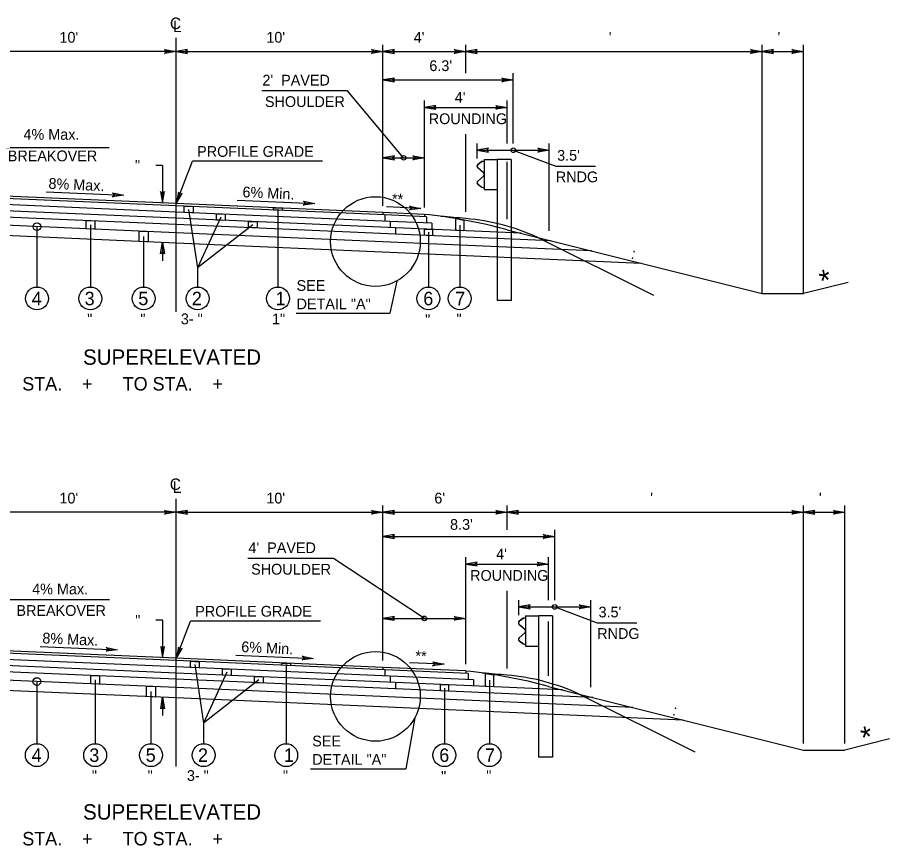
# Model space of a CAD drawing. Extents: x -592 to 1199, y -590 to 416.
# Drawn here: x 524 to 637.5, y -214.2 to -106.3 of the extents above; entities that cross this region are included whole.
import ezdxf

# ---------------------------------------------------------------- set-up
doc = ezdxf.new("R2010")
doc.units = 0
doc.layers.add('1', color=7, linetype='Continuous')
doc.layers.add('Des_ Drain_ Ftrs', color=7, linetype='Continuous')

msp = doc.modelspace()

# ---------------------------------------------------------------- linework, layer by layer
at = {"layer": '1'}
for p, q in [((544.62, -144.63), (544.62, -108.97)), ((571.56, -130.83), (571.56, -109.85)), ((582.34, -113.56), (582.34, -109.85)), ((620.92, -142.25), (620.92, -109.85)), ((626.31, -142.25), (626.31, -109.85)), ((544.62, -110.73), (517.68, -110.73)), ((544.62, -110.73), (571.56, -110.73)), ((571.56, -110.73), (582.34, -110.73)), ((582.34, -110.73), (620.92, -110.73)), ((620.92, -110.73), (626.31, -110.73)), ((588.53, -122.71), (588.53, -113.56)), ((571.56, -114.44), (588.53, -114.44)), ((566.92, -115.86), (555.78, -115.86)), ((574.25, -124.58), (566.92, -115.86)), ((576.95, -131.07), (576.95, -117.13)), ((576.95, -118.01), (587.72, -118.01)), ((587.72, -122.71), (587.72, -117.13)), ((582.34, -131.62), (582.34, -121.49)), ((535.9, -123.27), (521.95, -123.27)), ((583.84, -124.66), (583.84, -122.71)), ((583.84, -123.59), (593.22, -123.59)), ((588.53, -123.59), (594.09, -125.66)), ((593.22, -134.07), (593.22, -122.71)), ((571.56, -124.58), (576.95, -124.58)), ((584.75, -124.78), (584.75, -128.71)), ((584.75, -124.78), (586.43, -124.78)), ((586.43, -124.78), (586.43, -143.17)), ((588.26, -124.78), (586.43, -124.78)), ((588.26, -124.78), (588.26, -143.17)), ((542.84, -125.58), (541.96, -125.58)), ((542.84, -125.58), (542.84, -130.46)), ((544.63, -130.54), (546.75, -125.03)), ((563.67, -125.03), (546.75, -125.03)), ((583.9, -125.88), (584.63, -126.52)), ((584.43, -125.06), (583.92, -125.45)), ((583.92, -125.86), (584.65, -126.49)), ((584.45, -125.09), (583.94, -125.47)), ((584.75, -125), (584.43, -125.06)), ((584.75, -125.03), (584.45, -125.09)), ((587.72, -132.59), (587.72, -125.09)), ((594.09, -125.66), (599.24, -125.66)), ((584.63, -126.97), (583.9, -127.6)), ((584.65, -126.99), (583.92, -127.62)), ((584.72, -126.7), (584.72, -126.78)), ((584.75, -126.7), (584.75, -126.78)), ((583.92, -128.03), (584.43, -128.42)), ((583.94, -128.01), (584.45, -128.4)), ((544.62, -130.53), (517.67, -129.36)), ((527.7, -129.02), (537.81, -129.46)), ((584.43, -128.42), (584.75, -128.48)), ((584.45, -128.4), (584.75, -128.45)), ((584.75, -128.71), (586.43, -128.71)), ((544.62, -131.64), (516.41, -130.41)), ((544.62, -130.83), (517.33, -129.64)), ((571.56, -131.71), (544.62, -130.53)), ((552.57, -130.11), (562.68, -130.55)), ((544.62, -132.45), (515.49, -131.18)), ((571.8, -132.02), (544.62, -130.83)), ((572.5, -132.86), (544.62, -131.64)), ((546.25, -131.31), (547.42, -138.93)), ((557.88, -131.27), (557.88, -141.42)), ((576.95, -131.95), (571.56, -131.71)), ((571.56, -131.71), (571.56, -132.01)), ((576.5, -131.17), (572.01, -130.97)), ((544.62, -133.26), (515.49, -131.99)), ((573.21, -133.7), (544.62, -132.45)), ((550.43, -132.29), (547.42, -138.93)), ((577.24, -132.26), (571.8, -132.02)), ((571.8, -132.02), (571.8, -132.83)), ((577.93, -133.1), (572.5, -132.86)), ((572.5, -132.86), (572.5, -133.67)), ((576.95, -131.95), (576.95, -132.25)), ((577.24, -132.26), (577.24, -133.07)), ((583.84, -132.72), (583.84, -132.72)), ((544.62, -135.69), (492.81, -133.42)), ((544.62, -134.34), (515.49, -133.07)), ((526.5, -133.55), (526.5, -141.42)), ((533.46, -133.31), (533.46, -141.42)), ((573.21, -134.51), (544.62, -133.26)), ((554.6, -133.31), (547.42, -138.93)), ((573.21, -133.7), (573.21, -134.51)), ((589.56, -134.41), (573.21, -133.7)), ((577.93, -133.1), (577.93, -133.91)), ((581.56, -133.37), (581.56, -141.42)), ((587.72, -133.96), (620.92, -142.25)), ((540.39, -134.82), (540.39, -141.42)), ((571.56, -135.52), (544.62, -134.34)), ((593.48, -135.39), (573.21, -134.51)), ((577.48, -134.27), (577.48, -141.42)), ((591.72, -134.95), (606.77, -142.48)), ((542.84, -135.61), (542.84, -137.98)), ((605.24, -138.33), (544.62, -135.69)), ((598.71, -136.7), (571.56, -135.52)), ((547.42, -138.93), (547.42, -141.42)), ((573.35, -140.63), (572.47, -144.81)), ((632.14, -140.8), (626.31, -142.25)), ((620.92, -142.25), (626.31, -142.25)), ((588.26, -143.17), (586.43, -143.17)), ((560.24, -144.81), (572.47, -144.81)), ((544.62, -203.88), (544.62, -169)), ((571.56, -190.08), (571.56, -169.88)), ((587.72, -173.04), (587.72, -169.88)), ((626.31, -200.86), (626.31, -169.88)), ((631.7, -200.86), (631.7, -169.88)), ((544.62, -170.76), (517.68, -170.76)), ((544.62, -170.76), (571.56, -170.76)), ((571.56, -170.76), (587.72, -170.76)), ((587.72, -170.76), (626.31, -170.76)), ((626.31, -170.76), (631.7, -170.76)), ((593.92, -182.2), (593.92, -173.04)), ((571.56, -173.92), (593.92, -173.92)), ((565.13, -176.77), (553.98, -176.77)), ((576.95, -184.58), (565.13, -176.77)), ((582.34, -190.55), (582.34, -176.62)), ((593.11, -182.2), (593.11, -176.62)), ((582.34, -177.5), (593.11, -177.5)), ((587.72, -191.1), (587.72, -180.98)), ((535.94, -182.15), (522.46, -182.15)), ((589.23, -184.15), (589.23, -182.2)), ((598.61, -193.54), (598.61, -182.2)), ((589.23, -183.08), (598.61, -183.08)), ((593.92, -183.08), (599.47, -185.15)), ((542.87, -184.83), (541.99, -184.83)), ((542.87, -184.83), (542.87, -189.71)), ((544.63, -189.79), (546.5, -184.93)), ((563.42, -184.93), (546.5, -184.93)), ((571.56, -184.58), (582.34, -184.58)), ((589.82, -184.55), (589.31, -184.94)), ((589.84, -184.57), (589.32, -184.96)), ((590.14, -184.49), (589.82, -184.55)), ((590.14, -184.52), (589.84, -184.57)), ((590.14, -184.26), (590.14, -188.19)), ((590.14, -184.26), (591.82, -184.26)), ((591.82, -184.26), (591.82, -202.66)), ((593.65, -184.26), (591.82, -184.26)), ((593.11, -192.08), (593.11, -185)), ((593.65, -184.26), (593.65, -202.66)), ((589.29, -185.37), (590.02, -186)), ((589.31, -185.35), (590.04, -185.98)), ((590.11, -186.19), (590.11, -186.27)), ((590.14, -186.19), (590.14, -186.27)), ((599.47, -185.15), (604.63, -185.15)), ((590.02, -186.45), (589.29, -187.09)), ((590.04, -186.48), (589.31, -187.11)), ((526.9, -188.24), (537.01, -188.68)), ((589.31, -187.52), (589.82, -187.91)), ((589.32, -187.5), (589.84, -187.88)), ((589.82, -187.91), (590.14, -187.97)), ((589.84, -187.88), (590.14, -187.94)), ((590.14, -188.19), (591.82, -188.19)), ((544.62, -190.08), (517.33, -188.89)), ((544.62, -189.78), (517.67, -188.61)), ((552.41, -189.36), (562.52, -189.8)), ((544.62, -191.7), (515.49, -190.43)), ((544.62, -190.89), (516.41, -189.66)), ((571.56, -190.96), (544.62, -189.78)), ((571.8, -191.27), (544.62, -190.08)), ((547.05, -190.6), (548.21, -198.22)), ((558.96, -190.57), (558.96, -200.91)), ((579.53, -190.55), (575.03, -190.36)), ((544.62, -192.51), (515.5, -191.24)), ((572.5, -192.11), (544.62, -190.89)), ((573.21, -192.95), (544.62, -191.7)), ((551.22, -191.58), (548.21, -198.22)), ((582.34, -191.43), (571.56, -190.96)), ((571.56, -190.96), (571.56, -191.26)), ((582.66, -191.75), (571.8, -191.27)), ((571.8, -191.27), (571.8, -192.08)), ((582.34, -191.43), (582.34, -191.73)), ((582.66, -191.75), (582.66, -192.55)), ((544.62, -194.94), (487.82, -192.46)), ((544.62, -193.59), (515.49, -192.32)), ((526.49, -192.8), (526.49, -200.91)), ((534.08, -192.59), (534.08, -200.91)), ((573.21, -193.76), (544.62, -192.51)), ((555.4, -192.59), (548.21, -198.22)), ((583.36, -192.58), (572.5, -192.11)), ((572.5, -192.11), (572.5, -192.92)), ((573.21, -192.95), (573.21, -193.76)), ((594.95, -193.9), (573.21, -192.95)), ((583.36, -192.58), (583.36, -193.39)), ((585.43, -192.63), (585.43, -200.91)), ((589.23, -192.21), (589.23, -192.21)), ((541.35, -194.12), (541.35, -200.91)), ((573.17, -194.84), (544.62, -193.59)), ((598.87, -194.88), (573.21, -193.76)), ((579.56, -193.67), (579.56, -200.91)), ((593.11, -193.44), (626.31, -201.74)), ((542.87, -194.86), (542.87, -197.23)), ((610.63, -197.82), (544.62, -194.94)), ((604.1, -196.19), (573.17, -194.84)), ((597.11, -194.44), (612.16, -201.97)), ((575.71, -197.53), (574.53, -204.17)), ((548.21, -198.22), (548.21, -200.91)), ((637.53, -200.28), (631.7, -201.74)), ((626.31, -201.74), (631.7, -201.74)), ((593.65, -202.66), (591.82, -202.66)), ((562.13, -204.17), (574.53, -204.17))]:
    msp.add_line(p, q, dxfattribs=at)
for points in [[(545.68, -130.88), (546.83, -130.93), (546.83, -131.74), (545.68, -131.69)], [(557.31, -131.09), (558.45, -131.14), (558.45, -131.44), (557.31, -131.39)], [(532.89, -132.75), (534.04, -132.8), (534.04, -133.88), (532.89, -133.83)], [(549.86, -131.87), (551, -131.92), (551, -132.73), (549.86, -132.68)], [(554.03, -132.86), (555.18, -132.91), (555.18, -133.72), (554.03, -133.67)], [(581.04, -132.49), (582.08, -132.68), (582.08, -134.09), (581.04, -134.04)], [(576.96, -133.86), (578, -133.91), (578, -134.72), (576.96, -134.67)], [(539.82, -134.13), (540.97, -134.18), (540.97, -135.53), (539.82, -135.48)], [(546.48, -190.17), (547.62, -190.22), (547.62, -191.02), (546.48, -190.97)], [(558.38, -190.39), (559.53, -190.44), (559.53, -190.74), (558.38, -190.69)], [(550.65, -191.16), (551.8, -191.21), (551.8, -192.02), (550.65, -191.97)], [(584.91, -191.75), (585.95, -191.91), (585.95, -193.51), (584.91, -193.46)], [(533.51, -192.03), (534.65, -192.08), (534.65, -193.16), (533.51, -193.11)], [(554.83, -192.15), (555.97, -192.2), (555.97, -193.01), (554.83, -192.96)], [(540.77, -193.42), (541.92, -193.47), (541.92, -194.82), (540.77, -194.77)], [(579.03, -193.21), (580.08, -193.25), (580.08, -194.06), (579.03, -194.01)]]:
    msp.add_lwpolyline(points, close=True, dxfattribs=at)
for centre, radius in [((588.53, -123.59), 0.3), ((574.25, -124.58), 0.3), ((570.58, -135.49), 5.84), ((526.5, -133.55), 0.5), ((526.5, -142.9), 1.49), ((533.46, -142.9), 1.49), ((540.39, -142.9), 1.49), ((547.42, -142.9), 1.49), ((557.88, -142.9), 1.49), ((577.48, -142.9), 1.49), ((581.56, -142.9), 1.49), ((593.92, -183.08), 0.3), ((576.95, -184.58), 0.3), ((570.58, -194.74), 5.84), ((526.49, -192.8), 0.5), ((526.49, -202.39), 1.49), ((534.08, -202.39), 1.49), ((541.35, -202.39), 1.49), ((548.21, -202.39), 1.49), ((558.96, -202.39), 1.49), ((579.56, -202.39), 1.49), ((585.43, -202.39), 1.49)]:
    msp.add_circle(centre, radius, dxfattribs=at)
for centre, radius, start, end in [((584.08, -125.67), 0.278, 126.9799, 229.021), ((584.08, -125.67), 0.249, 126.9799, 229.021), ((584.47, -126.7), 0.249, 0, 49.0365), ((584.47, -126.78), 0.249, 310.9635, 0), ((584.47, -126.7), 0.278, 0, 49.0365), ((584.47, -126.78), 0.278, 310.9635, 0), ((584.08, -127.81), 0.278, 130.979, 233.0201), ((584.08, -127.81), 0.249, 130.979, 233.0201), ((570.06, -198.78), 67.19, 74.7593, 84.1179), ((571.51, -233.16), 101.24, 83.8633, 85.6775), ((580.21, -159.79), 27.37, 65.1374, 85.5513), ((589.47, -185.16), 0.278, 126.9799, 229.021), ((589.47, -185.16), 0.249, 126.9799, 229.021), ((589.86, -186.19), 0.249, 0, 49.0365), ((589.86, -186.19), 0.278, 0, 49.0365), ((589.47, -187.3), 0.278, 130.979, 233.0201), ((589.47, -187.3), 0.249, 130.979, 233.0201), ((589.86, -186.27), 0.249, 310.9635, 0), ((589.86, -186.27), 0.278, 310.9635, 0), ((575.45, -258.27), 67.19, 74.7602, 84.1188), ((576.9, -292.65), 101.24, 83.8633, 85.6775), ((585.6, -219.27), 27.37, 65.1374, 85.5513)]:
    msp.add_arc(centre, radius, start, end, dxfattribs=at)
at = {"layer": 'Des_ Drain_ Ftrs'}
for points in [[(544.62, -110.73), (543.13, -110.98), (543.42, -110.73), (543.13, -110.48)], [(544.62, -110.73), (546.11, -110.98), (545.81, -110.73), (546.11, -110.48)], [(571.56, -110.73), (570.07, -110.98), (570.37, -110.73), (570.07, -110.48)], [(571.56, -110.73), (573.05, -110.98), (572.75, -110.73), (573.05, -110.48)], [(582.34, -110.73), (580.85, -110.98), (581.14, -110.73), (580.85, -110.48)], [(582.34, -110.73), (583.82, -110.98), (583.53, -110.73), (583.82, -110.48)], [(620.92, -110.73), (619.43, -110.98), (619.73, -110.73), (619.43, -110.48)], [(620.92, -110.73), (622.41, -110.98), (622.12, -110.73), (622.41, -110.48)], [(626.31, -110.73), (624.82, -110.98), (625.12, -110.73), (624.82, -110.48)], [(571.56, -114.44), (573.04, -114.68), (572.75, -114.44), (573.04, -114.19)], [(588.53, -114.44), (587.04, -114.68), (587.33, -114.44), (587.04, -114.19)], [(576.95, -118.01), (578.44, -118.26), (578.14, -118.01), (578.44, -117.76)], [(587.72, -118.01), (586.24, -118.26), (586.53, -118.01), (586.24, -117.76)], [(583.84, -123.59), (585.32, -123.84), (585.03, -123.59), (585.32, -123.34)], [(593.22, -123.59), (591.73, -123.84), (592.03, -123.59), (591.73, -123.34)], [(571.56, -124.58), (573.05, -124.82), (572.75, -124.58), (573.05, -124.33)], [(576.95, -124.58), (575.46, -124.82), (575.75, -124.58), (575.46, -124.33)], [(537.81, -129.46), (536.31, -129.64), (536.62, -129.41), (536.33, -129.15)], [(542.84, -130.46), (543.09, -128.97), (542.84, -129.26), (542.59, -128.97)], [(544.63, -130.54), (545.39, -129.24), (545.05, -129.42), (544.93, -129.06)], [(562.68, -130.55), (561.18, -130.74), (561.49, -130.5), (561.21, -130.24)], [(576.5, -131.17), (575, -131.36), (575.31, -131.12), (575.02, -130.86)], [(542.84, -135.61), (543.09, -137.1), (542.84, -136.8), (542.59, -137.1)], [(544.62, -170.76), (543.13, -171.01), (543.42, -170.76), (543.13, -170.51)], [(544.62, -170.76), (546.11, -171.01), (545.81, -170.76), (546.11, -170.51)], [(571.56, -170.76), (570.07, -171.01), (570.37, -170.76), (570.07, -170.51)], [(571.56, -170.76), (573.05, -171.01), (572.75, -170.76), (573.05, -170.51)], [(587.72, -170.76), (586.24, -171.01), (586.53, -170.76), (586.24, -170.51)], [(587.72, -170.76), (589.21, -171.01), (588.92, -170.76), (589.21, -170.51)], [(626.31, -170.76), (624.82, -171.01), (625.12, -170.76), (624.82, -170.51)], [(626.31, -170.76), (627.8, -171.01), (627.5, -170.76), (627.8, -170.51)], [(631.7, -170.76), (630.21, -171.01), (630.51, -170.76), (630.21, -170.51)], [(571.56, -173.92), (573.04, -174.17), (572.75, -173.92), (573.04, -173.67)], [(593.92, -173.92), (592.43, -174.17), (592.72, -173.92), (592.43, -173.67)], [(582.34, -177.5), (583.82, -177.74), (583.53, -177.5), (583.82, -177.25)], [(593.11, -177.5), (591.62, -177.74), (591.92, -177.5), (591.62, -177.25)], [(589.23, -183.08), (590.71, -183.33), (590.42, -183.08), (590.71, -182.83)], [(598.61, -183.08), (597.12, -183.33), (597.42, -183.08), (597.12, -182.83)], [(571.56, -184.58), (573.05, -184.83), (572.75, -184.58), (573.05, -184.33)], [(582.34, -184.58), (580.85, -184.83), (581.14, -184.58), (580.85, -184.33)], [(537.01, -188.68), (535.51, -188.86), (535.82, -188.62), (535.53, -188.36)], [(542.87, -189.71), (543.12, -188.22), (542.87, -188.51), (542.63, -188.22)], [(544.63, -189.79), (545.39, -188.49), (545.05, -188.68), (544.93, -188.31)], [(562.52, -189.8), (561.03, -189.99), (561.33, -189.75), (561.05, -189.49)], [(579.53, -190.55), (578.03, -190.74), (578.33, -190.5), (578.05, -190.24)], [(542.87, -194.86), (543.12, -196.35), (542.87, -196.05), (542.63, -196.35)]]:
    msp.add_lwpolyline(points, close=True, dxfattribs=at)

# ---------------------------------------------------------------- texts
at = {"layer": '1'}
for s, height, p in [("10'", 1.4, (529.43, -109.58)), ("10'", 1.4, (556.37, -109.58)), ("4'", 1.4, (575.56, -109.58)), ("  '", 1.4, (599.93, -109.58)), (" '", 1.4, (622.42, -109.58)), ("6.3'", 1.4, (577.6, -113.28)), ("2'  PAVED", 1.4, (555.86, -115.16)), ('SHOULDER', 1.4, (556.19, -117.96)), ("4'", 1.4, (580.91, -117.39)), ('ROUNDING', 1.4, (577.52, -120.19)), ('4% Max.', 1.4, (524.75, -122.23)), ('BREAKOVER', 1.4, (522.7, -125.03)), ('PROFILE GRADE', 1.4, (547.36, -124.45)), ("3.5'", 1.4, (594.24, -124.96)), ('RNDG', 1.4, (594.07, -127.76)), ('SEE', 1.4, (560.31, -141.91)), ('4', 1.75, (525.82, -143.78)), ('3', 1.75, (532.71, -143.78)), ('5', 1.75, (539.7, -143.78)), ('2', 1.75, (546.67, -143.78)), ('1', 1.75, (557.58, -143.78)), ('DETAIL "A"', 1.4, (560.31, -144.31)), ('6', 1.75, (576.81, -143.78)), ('7', 1.75, (580.97, -143.78)), (' "', 1.4, (532.52, -146.26)), (' "', 1.4, (539.45, -146.26)), ('3- "', 1.4, (545.24, -146.26)), ('1"', 1.4, (557.11, -146.26)), (' "', 1.4, (576.53, -146.36)), (' "', 1.4, (580.61, -146.26)), ('SUPERELEVATED', 2, (532.5, -151.54)), ('STA.    +      TO STA.    +     ', 1.75, (524.59, -154.89)), ("10'", 1.4, (529.43, -169.61)), ("10'", 1.4, (556.37, -169.61)), ("6'", 1.4, (578.25, -169.61)), ("  '", 1.4, (605.32, -169.61)), (" '", 1.4, (627.81, -169.61)), ("8.3'", 1.4, (580.3, -173.04)), ("4'  PAVED", 1.4, (554.04, -176.07)), ("4'", 1.4, (586.3, -176.88)), ('SHOULDER', 1.4, (554.39, -178.87)), ('ROUNDING', 1.4, (582.91, -179.68)), ('4% Max.', 1.4, (525.88, -181.45)), ('BREAKOVER', 1.4, (523.83, -184.25)), ('PROFILE GRADE', 1.4, (547.11, -184.35)), ("3.5'", 1.4, (599.63, -184.45)), ('RNDG', 1.4, (599.46, -187.25)), ('SEE', 1.4, (562.35, -201.25)), ('4', 1.75, (525.81, -203.27)), ('3', 1.75, (533.32, -203.27)), ('5', 1.75, (540.66, -203.27)), ('2', 1.75, (547.47, -203.27)), ('1', 1.75, (558.66, -203.27)), ('6', 1.75, (578.89, -203.27)), ('7', 1.75, (584.84, -203.27)), ('DETAIL "A"', 1.4, (562.35, -203.65)), (' "', 1.4, (533.13, -205.75)), (' "', 1.4, (540.4, -205.75)), ('3- "', 1.4, (546.03, -205.75)), (' "', 1.4, (558.01, -205.75)), (' "', 1.4, (584.49, -205.75)), (' "', 1.4, (578.61, -205.85)), ('SUPERELEVATED', 2, (532.5, -210.79)), ('STA.    +      TO STA.    +     ', 1.75, (524.59, -214.15))]:
    msp.add_text(s, height=height, dxfattribs=at).set_placement(p)
for s, height, rotation, p in [('  "', 1.4, 0.1438, (538.23, -126.28)), ('8% Max.', 1.4, 357.3762, (527.98, -128.6)), ('6% Min.', 1.4, 357.3731, (553.24, -129.71)), ('**', 1.4, 357.2164, (572.69, -130.61)), (' : ', 1.4, 345.7718, (603.27, -137.55)), ('*', 2.8, 12.8479, (628.77, -142.06)), ('  "', 1.4, 0.1438, (538.26, -185.53)), ('8% Max.', 1.4, 357.3763, (527.18, -187.82)), ('6% Min.', 1.4, 357.3728, (553.08, -188.96)), ('**', 1.4, 357.2162, (575.74, -190.15)), (' : ', 1.4, 345.7718, (608.66, -197.04)), ('*', 2.8, 12.8479, (634.16, -201.55))]:
    msp.add_text(s, height=height, rotation=rotation, dxfattribs=at).set_placement(p)
at = {"layer": 'Des_ Drain_ Ftrs'}
for s, p in [('C', (543.82, -107.81)), ('L', (544.22, -108.21)), ('C', (543.8, -167.85)), ('L', (544.19, -168.24))]:
    msp.add_text(s, height=1.5, dxfattribs=at).set_placement(p)

doc.saveas('drawing.dxf')
